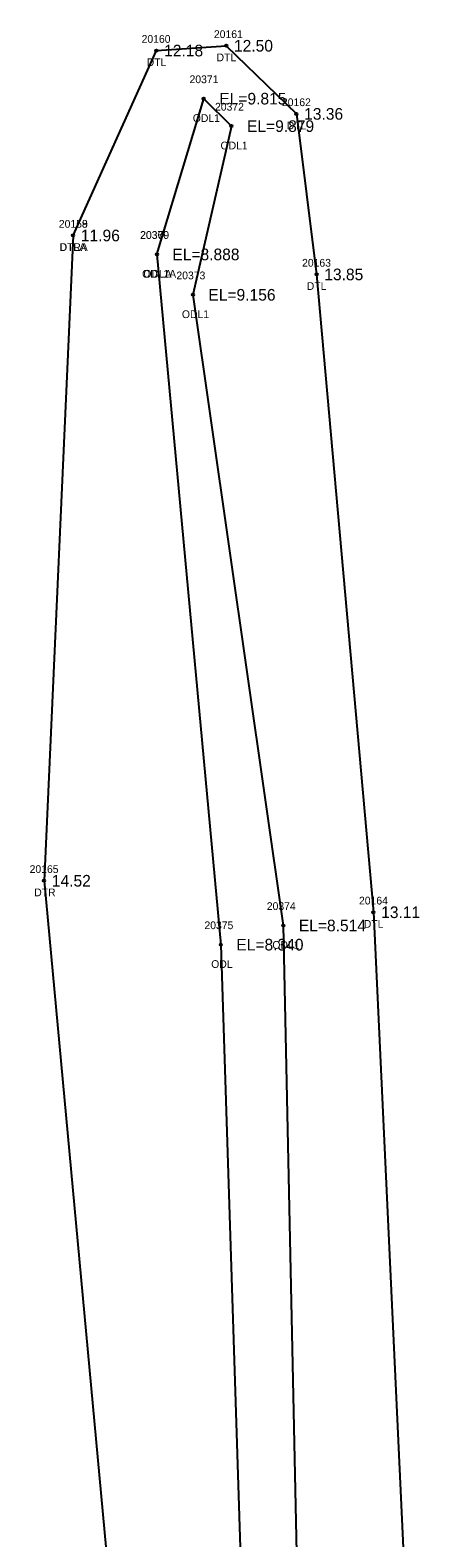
# Model space of a CAD drawing. Extents: x 2072302 to 2072980, y 127650 to 129736.
# Drawn here: x 2072391.9 to 2072444.3, y 127845.3 to 128039.7 of the extents above; entities that cross this region are included whole.
import ezdxf

# ---------------------------------------------------------------- set-up
doc = ezdxf.new("R2010")
doc.units = 0
for name, color, linetype in [('RD_EX_H2O', 7, 'Continuous'), ('RD_EX_H2O_txCode', 7, 'Continuous'), ('RD_EX_TX_H2O_ELEV', 7, 'Continuous'), ('RD_SMD_Locator', 7, 'Continuous')]:
    doc.layers.add(name, color=color, linetype=linetype)

msp = doc.modelspace()

# ---------------------------------------------------------------- linework, layer by layer
at = {"layer": 'RD_EX_H2O'}
for points in [[(2072397.43, 128013.21), (2072408.15, 128037.05), (2072417.14, 128037.67), (2072426.18, 128028.89), (2072428.77, 128008.19), (2072436.1, 127925.95), (2072440.16, 127839.38), (2072444.26, 127746.21), (2072439.54, 127661.97), (2072428.72, 127652.16), (2072418.72, 127654.12), (2072416.39, 127665.39)], [(2072408.21, 128010.77), (2072414.25, 128030.85), (2072417.82, 128027.31), (2072412.85, 128005.56), (2072424.49, 127924.24), (2072426.33, 127837.29), (2072432.47, 127745.76), (2072432.14, 127664.56)], [(2072397.43, 128013.21), (2072393.69, 127930.01), (2072402.33, 127836.68), (2072410.62, 127737.08), (2072416.39, 127665.39)], [(2072408.21, 128010.77), (2072416.45, 127921.77), (2072419.21, 127836.01), (2072424.85, 127745.31), (2072424.07, 127665.21)]]:
    msp.add_lwpolyline(points, dxfattribs=at)
at = {"layer": 'RD_SMD_Locator'}
for centre in [(2072408.15, 128037.05), (2072417.14, 128037.67), (2072414.25, 128030.85), (2072417.82, 128027.31), (2072426.18, 128028.89), (2072397.43, 128013.21), (2072397.43, 128013.21), (2072408.21, 128010.77), (2072408.21, 128010.77), (2072428.77, 128008.19), (2072412.85, 128005.56), (2072393.69, 127930.01), (2072436.1, 127925.95), (2072424.49, 127924.24), (2072416.45, 127921.77)]:
    msp.add_circle(centre, 0.15, dxfattribs=at)

# ---------------------------------------------------------------- texts
at = {"layer": 'RD_EX_H2O_txCode'}
for s, p in [('20161', (2072415.56, 128038.67)), ('20160', (2072406.25, 128038.05)), ('DTL', (2072406.91, 128035.05)), ('DTL', (2072415.9, 128035.67)), ('20371', (2072412.42, 128032.85)), ('20372', (2072415.7, 128029.31)), ('20162', (2072424.32, 128029.89)), ('ODL1', (2072412.84, 128027.85)), ('DTL', (2072424.94, 128026.89)), ('ODL1', (2072416.41, 128024.31)), ('20158', (2072395.59, 128014.21)), ('20159', (2072395.59, 128014.21)), ('DTRA', (2072395.67, 128011.21)), ('DTLA', (2072395.7, 128011.21)), ('20370', (2072406.05, 128012.77)), ('20369', (2072406.07, 128012.77)), ('20163', (2072426.91, 128009.19)), ('ODL1A', (2072406.31, 128007.77)), ('ODLA', (2072406.48, 128007.77)), ('20373', (2072410.73, 128007.56)), ('DTL', (2072427.52, 128006.19)), ('ODL1', (2072411.44, 128002.56)), ('20165', (2072391.83, 127931.01)), ('DTR', (2072392.42, 127928.01)), ('20374', (2072422.37, 127926.24)), ('20164', (2072434.24, 127926.95)), ('20375', (2072414.34, 127923.77)), ('DTL', (2072434.86, 127923.95)), ('ODL1', (2072423.08, 127921.24)), ('ODL', (2072415.21, 127918.77))]:
    msp.add_text(s, height=1, dxfattribs=at).set_placement(p)
at = {"layer": 'RD_EX_TX_H2O_ELEV'}
for s, p in [('12.18', (2072409.15, 128036.3)), ('12.50', (2072418.14, 128036.92)), ('EL=9.815', (2072416.25, 128030.1)), ('13.36', (2072427.18, 128028.14)), ('EL=9.879', (2072419.82, 128026.56)), ('11.96', (2072398.43, 128012.46)), ('11.96', (2072398.43, 128012.46)), ('EL=8.888', (2072410.21, 128010.02)), ('EL=8.888', (2072410.21, 128010.02)), ('13.85', (2072429.77, 128007.44)), ('EL=9.156', (2072414.85, 128004.81)), ('14.52', (2072394.69, 127929.26)), ('13.11', (2072437.1, 127925.2)), ('EL=8.514', (2072426.49, 127923.49)), ('EL=8.340', (2072418.45, 127921.02))]:
    msp.add_text(s, height=1.5, dxfattribs=at).set_placement(p)

doc.saveas('drawing.dxf')
